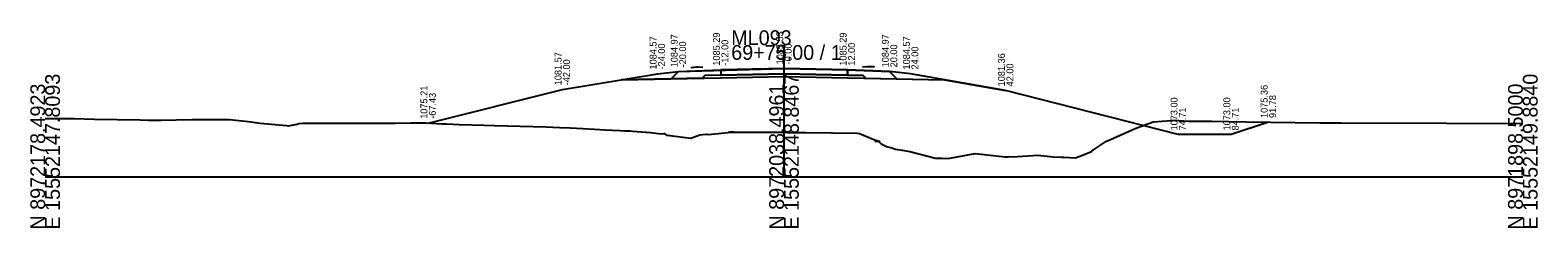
# Model space of a CAD drawing. Extents: x -26 to 14283, y -10 to 28.
# Drawn here: x 6997.2 to 7282.8, y -9.7 to 27.8 of the extents above; entities that cross this region are included whole.
import ezdxf

# ---------------------------------------------------------------- set-up
doc = ezdxf.new("R2010")
doc.units = 0
for name, color, linetype in [('Default', 7, 'Continuous'), ('dsn3DCenterLine', 7, 'Continuous'), ('dsn3DDitchBack', 7, 'Continuous'), ('dsn3DDitchFront', 7, 'Continuous'), ('dsn3DForeSlopeBarnRoofPoint', 7, 'Continuous'), ('dsn3DForeSlopeBreakLine', 7, 'Continuous'), ('dsn3DGroundLineIntercept', 7, 'Continuous'), ('dsn3DPavementTop', 7, 'Continuous'), ('dsn3DShoulderTop', 7, 'Continuous'), ('dsn3DSubgradeBreakLine', 7, 'Continuous'), ('dsn3DSubgradeHingePoint', 7, 'Continuous'), ('dsnGeopakCellCrossSection', 7, 'Continuous'), ('dsnXSEarthwork', 7, 'Continuous'), ('dsnXsExistingGround', 7, 'Continuous'), ('dsnXsPCCPavement', 7, 'Continuous'), ('dsnXsShldrEarthFill', 7, 'Continuous'), ('dsnXsShldrGranular', 7, 'Continuous'), ('dsnXsSideSlopes', 7, 'Continuous'), ('dsnXsSubbase', 7, 'Continuous'), ('dsnXsTextOffsetElevFinGrd', 7, 'Continuous'), ('SurBridge', 7, 'Continuous'), ('SurSurveyPoints', 7, 'Continuous')]:
    doc.layers.add(name, color=color, linetype=linetype)

msp = doc.modelspace()

# ---------------------------------------------------------------- linework, layer by layer
at = {"layer": 'Default'}
for points in [[(7120, 19.97), (7120, 19.97), (7140, 20.53), (7152, 20.29), (7160, 19.97)], [(7109.16, 18.43), (7128, 18.79), (7140, 19.03), (7152, 18.79), (7170.4, 18.43), (7182, 16.36)]]:
    msp.add_lwpolyline(points, dxfattribs=at)
at = {"layer": 'dsnGeopakCellCrossSection'}
for p, q in [((7140, 0), (7140, 25)), ((7000, 0), (7140, 0)), ((7140, 0), (7280, 0))]:
    msp.add_line(p, q, dxfattribs=at)
at = {"layer": 'dsnXSEarthwork'}
msp.add_lwpolyline([(7120, 19.97), (7128, 20.29), (7140, 20.53), (7152, 20.29), (7160, 19.97)], dxfattribs=at)
at = {"layer": 'dsnXsExistingGround'}
msp.add_lwpolyline([(7000, 11.06), (7001.67, 11.06), (7005.47, 11.04), (7009.35, 10.94), (7017.98, 10.81), (7019.57, 10.73), (7020.76, 10.75), (7021.85, 10.76), (7021.89, 10.76), (7027.79, 10.9), (7028.72, 10.89), (7034.96, 10.85), (7038.5, 10.52), (7040.27, 10.25), (7040.35, 10.24), (7040.72, 10.21), (7045.7, 9.75), (7046.05, 9.7), (7046.14, 9.7), (7047.68, 9.97), (7047.77, 10), (7048.06, 10.12), (7048.85, 10.16), (7049.85, 10.21), (7060.08, 10.16), (7066.34, 10.21), (7069.24, 10.23), (7072.12, 10.24), (7075.14, 10.06), (7076.12, 10.03), (7078.47, 9.95), (7080.83, 9.88), (7083.18, 9.81), (7085.15, 9.72), (7094.85, 9.51), (7097.53, 9.37), (7099.46, 9.27), (7101.88, 9.15), (7104.12, 9.04), (7106.06, 8.94), (7108.95, 8.8), (7108.96, 8.8), (7110.17, 8.74), (7110.42, 8.74), (7110.49, 8.74), (7114.68, 8.42), (7116.21, 8.24), (7117.29, 8.14), (7117.29, 8.22), (7117.74, 7.89), (7118.35, 7.87), (7122.37, 7.31), (7124.08, 7.98), (7124.6, 8.03), (7125.3, 8.1), (7125.44, 8.09), (7125.64, 8.06), (7130.03, 8.48), (7130.8, 8.48), (7131.16, 8.48), (7131.17, 8.48), (7136.1, 8.46), (7136.21, 8.46), (7141.04, 8.45), (7141.25, 8.44), (7143.91, 8.43), (7144.11, 8.42), (7144.11, 8.42), (7149.02, 8.34), (7149.19, 8.34), (7153.86, 8.26), (7154.32, 8.22), (7157.04, 7.08), (7157.56, 6.9), (7157.84, 6.75), (7158.41, 6.29), (7159.41, 5.73), (7160.44, 5.5), (7161.15, 5.23), (7162.38, 5.07), (7163.82, 4.8), (7168.71, 3.57), (7169.99, 3.53), (7171.09, 3.5), (7176.21, 4.42), (7181.89, 3.8), (7182.47, 3.8), (7182.76, 3.83), (7183.32, 3.77), (7188.07, 4.14), (7191.01, 3.81), (7192.6, 3.73), (7193, 3.71), (7195.23, 3.59), (7196.59, 4.12), (7198.26, 4.78), (7198.67, 5.15), (7200.91, 6.67), (7201.1, 6.76), (7201.32, 6.85), (7206.54, 9.2), (7209.96, 10.45), (7212.55, 10.64), (7213.95, 10.73), (7216.58, 10.59), (7221.05, 10.58), (7227.52, 10.41), (7241.56, 10.24), (7245.66, 10.24), (7265.53, 10.21), (7280, 10.14)], dxfattribs=at)
at = {"layer": 'dsnXsPCCPavement'}
msp.add_lwpolyline([(7128, 20.29), (7128, 20.29), (7128, 19.29), (7128, 19.29), (7128, 19.29), (7140, 19.53), (7152, 19.29), (7152, 19.29), (7152, 19.29), (7152, 20.29), (7152, 20.29), (7140, 20.53), (7128, 20.29)], dxfattribs=at)
at = {"layer": 'dsnXsShldrEarthFill'}
for points in [[(7118.64, 18.61), (7109.16, 18.43)], [(7161.36, 18.61), (7170.4, 18.43)]]:
    msp.add_lwpolyline(points, dxfattribs=at)
at = {"layer": 'dsnXsShldrGranular'}
for points in [[(7120, 19.97), (7128, 20.29), (7128, 19.29), (7128, 19.29), (7125, 19.23), (7125, 19.23), (7124.49, 18.72), (7124.49, 18.72), (7118.64, 18.61), (7118.64, 18.61), (7118.64, 18.61), (7120, 19.97), (7120, 19.97)], [(7160, 19.97), (7152, 20.29), (7152, 19.29), (7152, 19.29), (7155, 19.23), (7155, 19.23), (7155.51, 18.72), (7155.51, 18.72), (7161.36, 18.61), (7161.36, 18.61), (7161.36, 18.61), (7160, 19.97), (7160, 19.97)]]:
    msp.add_lwpolyline(points, dxfattribs=at)
at = {"layer": 'dsnXsSideSlopes'}
for points in [[(7072.57, 10.21), (7098, 16.57), (7098, 16.57), (7098, 16.57), (7116, 19.57), (7116, 19.57), (7120, 19.97)], [(7231.78, 10.36), (7224.71, 8), (7224.71, 8), (7214.71, 8), (7214.71, 8), (7182, 16.36), (7182, 16.36), (7182, 16.36), (7164, 19.57), (7164, 19.57), (7160, 19.97)]]:
    msp.add_lwpolyline(points, dxfattribs=at)
at = {"layer": 'dsnXsSubbase'}
msp.add_lwpolyline([(7124.49, 18.72), (7124.49, 18.72), (7124.49, 18.72), (7128, 18.79), (7128, 18.79), (7140, 19.03), (7152, 18.79), (7152, 18.79), (7155.51, 18.72), (7155.51, 18.72), (7155.51, 18.72), (7155, 19.23), (7155, 19.23), (7152, 19.29), (7152, 19.29), (7140, 19.53), (7128, 19.29), (7128, 19.29), (7125, 19.23), (7125, 19.23), (7124.49, 18.72)], dxfattribs=at)
at = {"layer": 'SurBridge'}
for points in [[(7122.33, 20.73), (7122.39, 20.75), (7123.4, 20.87), (7123.55, 20.88), (7123.72, 20.86), (7124.62, 20.79)], [(7157.12, 20.8), (7156.93, 20.86), (7156.72, 20.88), (7155.93, 20.9), (7155.75, 20.9), (7154.87, 20.82)]]:
    msp.add_lwpolyline(points, dxfattribs=at)
at = {"layer": 'SurSurveyPoints'}
for points in [[(7109.86, 8.73), (7110.8, 8.73)], [(7130.53, 8.48), (7129.53, 8.48)], [(7140.69, 8.44), (7141.64, 8.44)], [(7157.23, 6.79), (7158.2, 6.79)]]:
    msp.add_lwpolyline(points, dxfattribs=at)

# ---------------------------------------------------------------- texts
msp.add_text('-', height=0.0001).set_placement((7000, 0))
at = {"layer": 'dsn3DCenterLine'}
msp.add_text('X', height=0.00781, dxfattribs=at).set_placement((7140, 20.53))
at = {"layer": 'dsn3DDitchBack'}
msp.add_text('X', height=0.00781, dxfattribs=at).set_placement((7224.7, 8))
at = {"layer": 'dsn3DDitchFront'}
msp.add_text('X', height=0.00781, dxfattribs=at).set_placement((7214.7, 8))
at = {"layer": 'dsn3DForeSlopeBarnRoofPoint'}
for p in [(7098, 16.57), (7182, 16.36)]:
    msp.add_text('X', height=0.00781, dxfattribs=at).set_placement(p)
at = {"layer": 'dsn3DForeSlopeBreakLine'}
for p in [(7116, 19.57), (7164, 19.57)]:
    msp.add_text('X', height=0.00781, dxfattribs=at).set_placement(p)
at = {"layer": 'dsn3DGroundLineIntercept'}
for p in [(7072.56, 10.21), (7231.77, 10.35)]:
    msp.add_text('X', height=0.00781, dxfattribs=at).set_placement(p)
at = {"layer": 'dsn3DPavementTop'}
for p in [(7128, 20.29), (7152, 20.29)]:
    msp.add_text('X', height=0.00781, dxfattribs=at).set_placement(p)
at = {"layer": 'dsn3DShoulderTop'}
for p in [(7120, 19.97), (7160, 19.97)]:
    msp.add_text('X', height=0.00781, dxfattribs=at).set_placement(p)
at = {"layer": 'dsn3DSubgradeBreakLine'}
for p in [(7128, 18.79), (7140, 19.03), (7152, 18.79)]:
    msp.add_text('X', height=0.00781, dxfattribs=at).set_placement(p)
at = {"layer": 'dsn3DSubgradeHingePoint'}
for p in [(7109.16, 18.43), (7170.39, 18.43)]:
    msp.add_text('X', height=0.00781, dxfattribs=at).set_placement(p)
at = {"layer": 'dsnGeopakCellCrossSection'}
for s, p in [('ML093', (7130, 25)), ('69+75.00 / 1', (7130, 22.2))]:
    msp.add_text(s, height=2.8, dxfattribs=at).set_placement(p)
for s, p in [('N 8972178.4923', (7000, -10)), ('E 15552147.8093', (7002.8, -10)), ('N 8972038.4961', (7140, -10)), ('E 15552148.8467', (7142.8, -10)), ('N 8971898.5000', (7280, -10)), ('E 15552149.8840', (7282.8, -10))]:
    msp.add_text(s, height=2.8, rotation=90, dxfattribs=at).set_placement(p)
at = {"layer": 'dsnXsTextOffsetElevFinGrd'}
for s, p in [('1084.57', (7115.85, 20.37)), ('1084.97', (7119.85, 20.77)), ('1084.97', (7119.85, 20.77)), ('1085.29', (7127.85, 21.09)), ('1085.29', (7127.85, 21.09)), ('-12.00', (7129.45, 21.09)), ('-12.00', (7129.45, 21.09)), ('1085.53', (7139.85, 21.33)), ('1085.29', (7151.85, 21.09)), ('1085.29', (7151.85, 21.09)), ('1084.97', (7159.85, 20.77)), ('1084.57', (7163.85, 20.37)), ('1081.57', (7097.85, 17.37)), ('-24.00', (7117.45, 20.37)), ('-20.00', (7121.45, 20.77)), ('-20.00', (7121.45, 20.77)), ('-0.00', (7141.45, 21.33)), ('12.00', (7153.45, 21.09)), ('12.00', (7153.45, 21.09)), ('20.00', (7161.45, 20.77)), ('24.00', (7165.45, 20.37)), ('1081.36', (7181.85, 17.16)), ('-42.00', (7099.45, 17.37)), ('42.00', (7183.45, 17.16)), ('1075.21', (7072.42, 11.01)), ('1075.36', (7231.63, 11.16)), ('1075.36', (7231.63, 11.16)), ('-67.43', (7074.02, 11.01)), ('1073.00', (7214.56, 8.8)), ('1073.00', (7224.56, 8.8)), ('91.78', (7233.23, 11.16)), ('91.78', (7233.23, 11.16)), ('74.71', (7216.16, 8.8)), ('84.71', (7226.16, 8.8))]:
    msp.add_text(s, height=1.3, rotation=90, dxfattribs=at).set_placement(p)

doc.saveas('drawing.dxf')
